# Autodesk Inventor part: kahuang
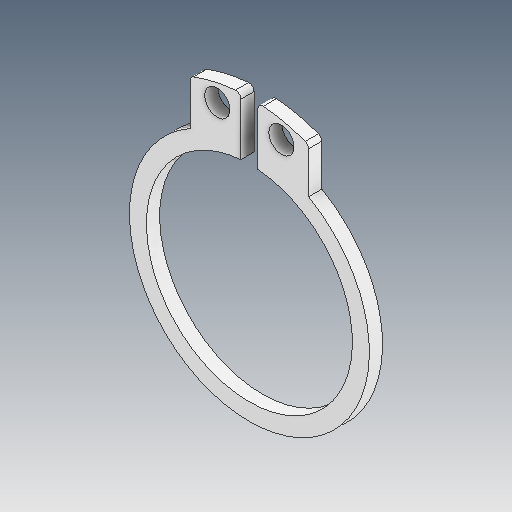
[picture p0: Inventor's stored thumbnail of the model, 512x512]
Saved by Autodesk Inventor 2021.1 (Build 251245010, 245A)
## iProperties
Created: 2021-05
Part Number: kahuang
Material: Ogólny
Document SubType Name: Modeling
Designer: user
Density: 1 g/cm^3
Appearance: Domyślna
Author: user
Revision Number: ÈÎºÎ
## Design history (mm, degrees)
feature "ÊäÈë1"
node "Bryła1"
